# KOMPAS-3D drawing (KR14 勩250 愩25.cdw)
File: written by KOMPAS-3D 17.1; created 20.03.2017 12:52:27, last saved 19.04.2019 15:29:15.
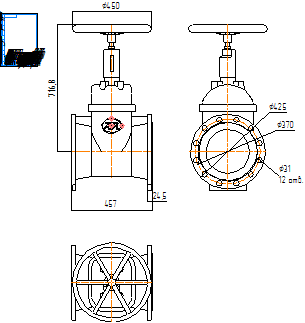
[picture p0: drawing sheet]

Sheet 1: A4, portrait

Title block, sheet 1: name: KR14 Ду250 Ру25; material: Внимание! Данный продукт является объектом авторского права ООО «Торговый Дом АДЛ». / Запрещается изменение, копирование, распространение / (в том числе путем копирования на другие сайты и ресурсы в Интернете) / или любое иное использование информации и объектов без предварительного / согласия правообладателя (ООО «Торговый Дом АДЛ»).; mass: 508; sheets: 1; organisation: ООО "Торговый дом АДЛ"; sheet format: A4; stored path: C:\Users\kka\KOMPAS_Work\!Trash\Задвижки ГРАНАР с приводами\KR14 Ду350 Ру16.cdw

Views: Вид 1, Проекционный вид 2, Проекционный вид 3
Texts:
  Klimkovich
  ADL
Dimensions and other numbers on the sheet: 450; 716,8; 24,5; 457; 425; 370; 31; 12 отв.; 1:1; 1; 508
